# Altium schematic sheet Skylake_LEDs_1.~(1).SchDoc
size 431 x 279 mm; Date: Not shown in title block; ApprovedBy: Not shown in title block; CheckedBy: Not shown in title block; Author: Not shown in title block; CompanyName: Not shown in title block; Engineer: Not shown in title block; Organization: Not shown in title block; Address1: Not shown in title block; Address2: Not shown in title block; Address3: Not shown in title block; Address4: Not shown in title block; DocumentNumber: 1; Revision: Use project parameter SCH_Rev; SheetNumber: 5; SheetTotal: 9; PageSetup: Record=PageOptions|CenterHorizontal=True|CenterVertical=True|PrintScale=1.00|XCorrection=1.00|YCorrection=1.00|PrintKind=0|BorderSize=5000000|LeftOffset=0|BottomOffset=0|Orientation=2|PaperLength=1000|PaperWidth=1000|Scale=100|PaperSource=15|PrintQuality=600|MediaType=1|DitherType=10|PaperKind=Letter|PrintScaleMode=1
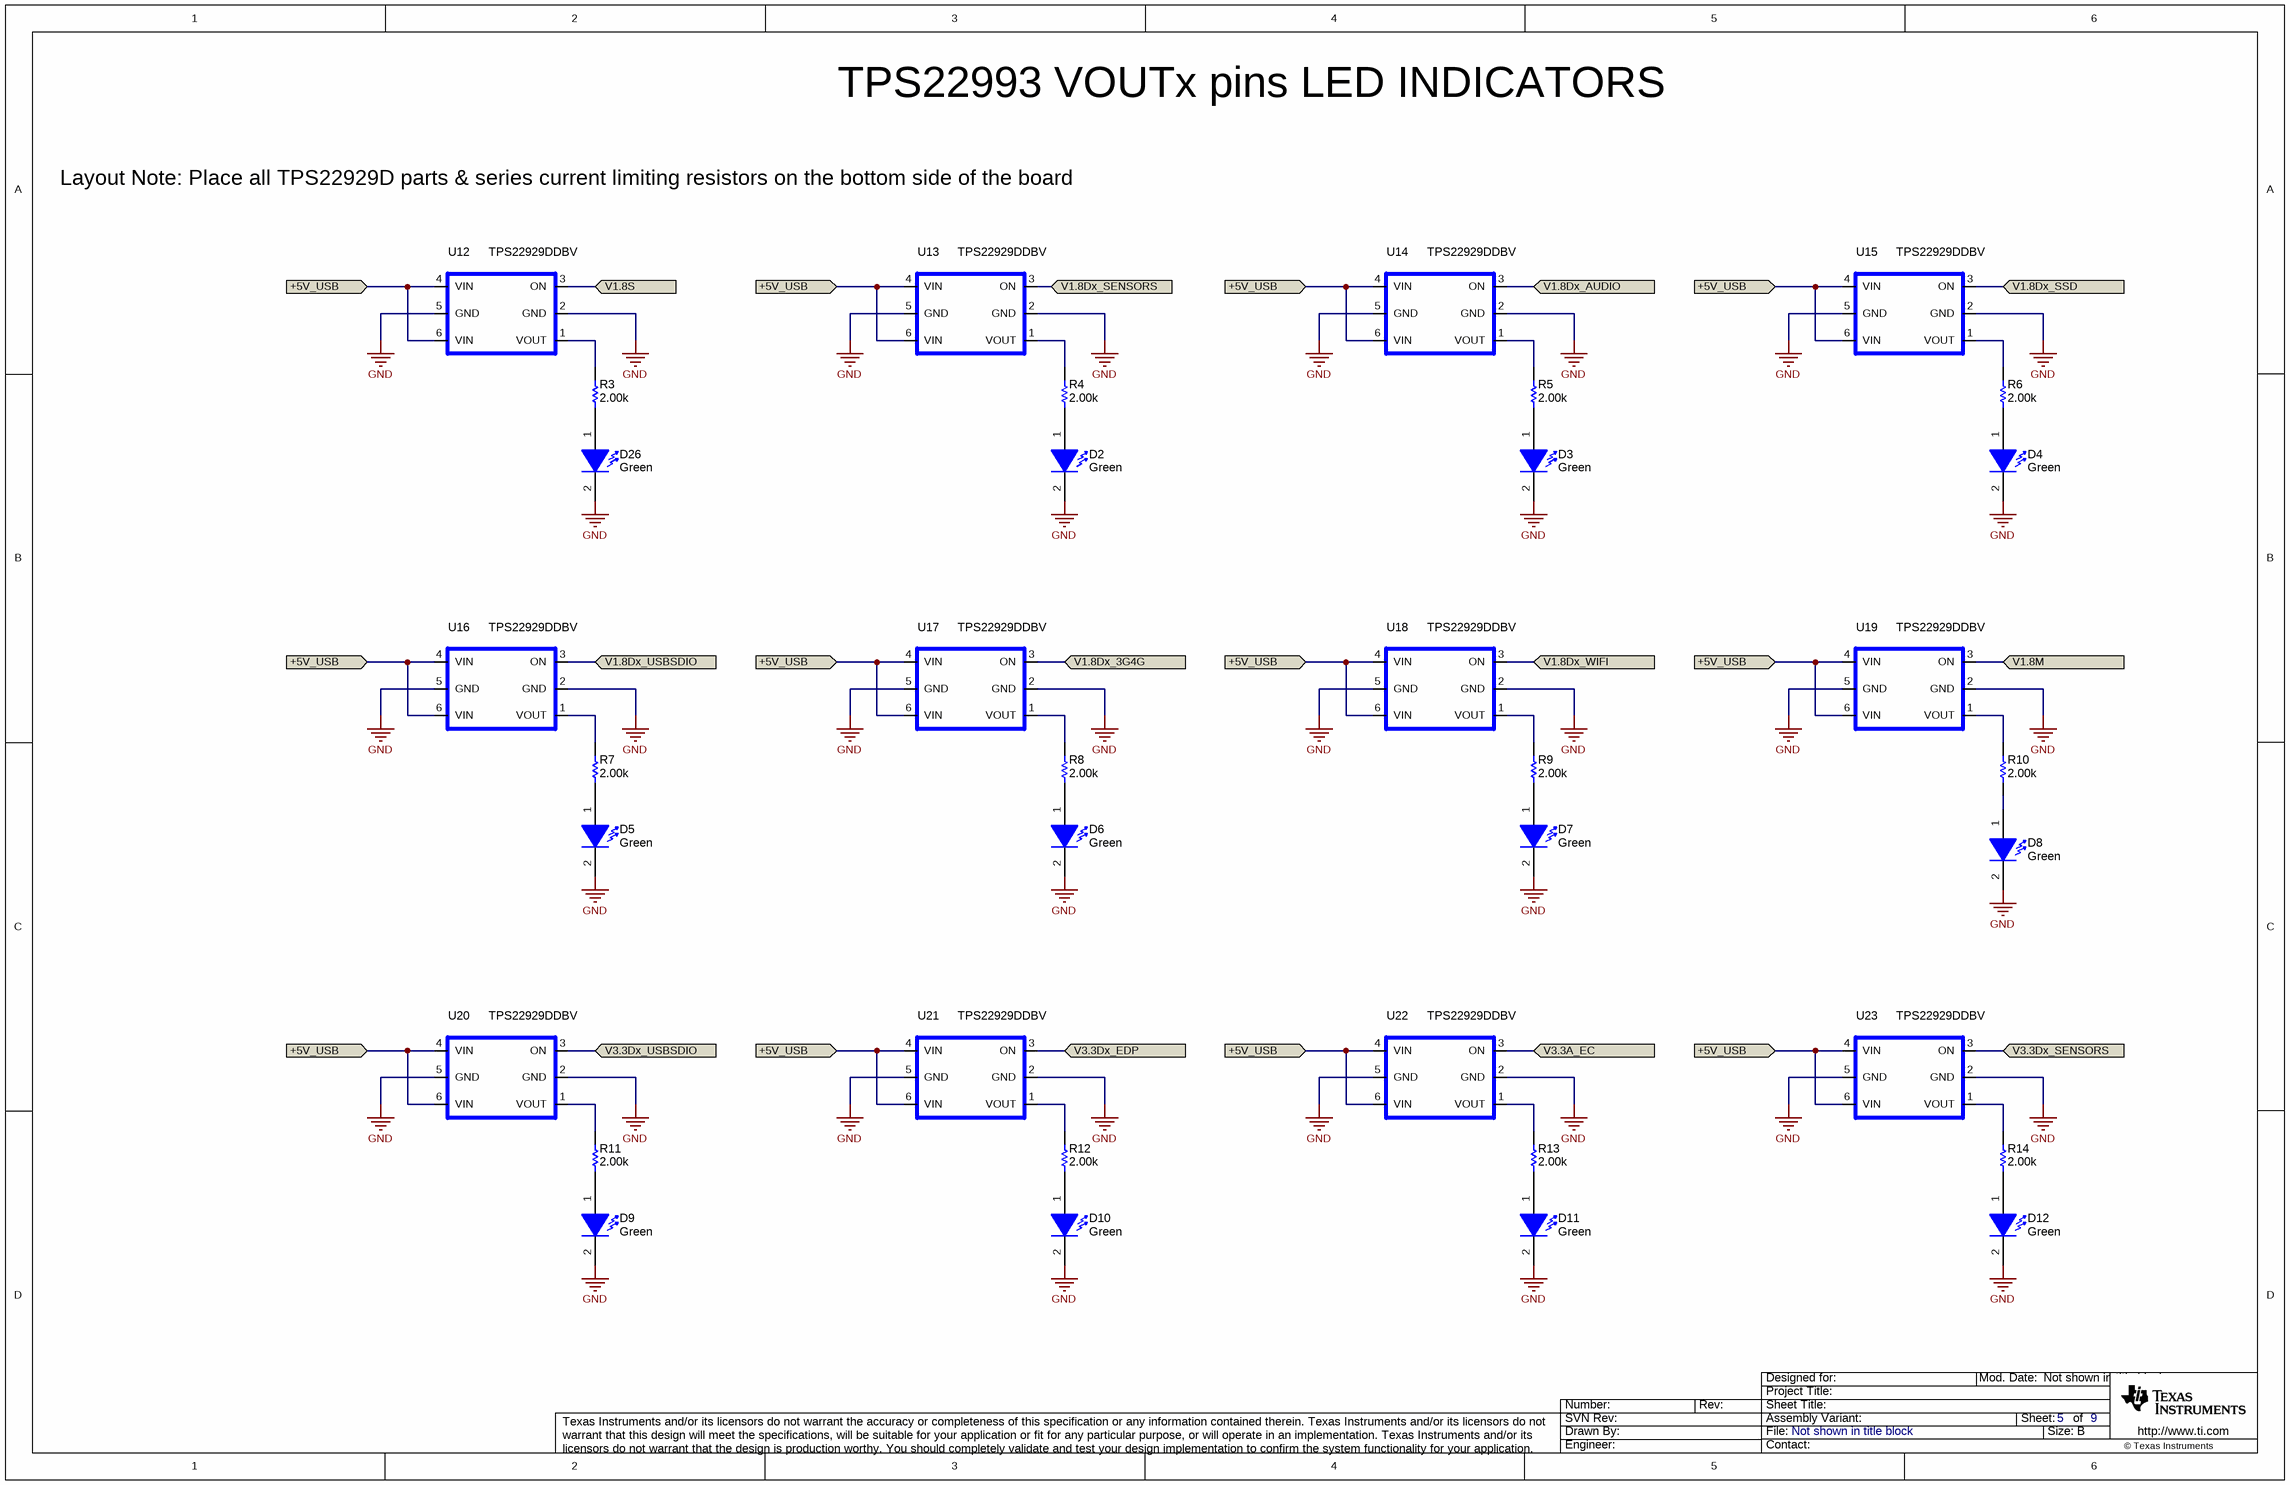
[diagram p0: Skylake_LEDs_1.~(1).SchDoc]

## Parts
D2  value Green  [LED_SML]  (hidden comment: SML312ECTT86)
D3  value Green  [LED_SML]  (hidden comment: SML312ECTT86)
D4  value Green  [LED_SML]  (hidden comment: SML312ECTT86)
D5  value Green  [LED_SML]  (hidden comment: SML312ECTT86)
D6  value Green  [LED_SML]  (hidden comment: SML312ECTT86)
D7  value Green  [LED_SML]  (hidden comment: SML312ECTT86)
D8  value Green  [LED_SML]  (hidden comment: SML312ECTT86)
D9  value Green  [LED_SML]  (hidden comment: SML312ECTT86)
D10  value Green  [LED_SML]  (hidden comment: SML312ECTT86)
D11  value Green  [LED_SML]  (hidden comment: SML312ECTT86)
D12  value Green  [LED_SML]  (hidden comment: SML312ECTT86)
D26  value Green  [LED_SML]  (hidden comment: SML312ECTT86)
R3  value 2.00k  [0603]  (hidden comment: CRCW06032K00FKEA)
R4  value 2.00k  [0603]  (hidden comment: CRCW06032K00FKEA)
R5  value 2.00k  [0603]  (hidden comment: CRCW06032K00FKEA)
R6  value 2.00k  [0603]  (hidden comment: CRCW06032K00FKEA)
R7  value 2.00k  [0603]  (hidden comment: CRCW06032K00FKEA)
R8  value 2.00k  [0603]  (hidden comment: CRCW06032K00FKEA)
R9  value 2.00k  [0603]  (hidden comment: CRCW06032K00FKEA)
R10  value 2.00k  [0603]  (hidden comment: CRCW06032K00FKEA)
R11  value 2.00k  [0603]  (hidden comment: CRCW06032K00FKEA)
R12  value 2.00k  [0603]  (hidden comment: CRCW06032K00FKEA)
R13  value 2.00k  [0603]  (hidden comment: CRCW06032K00FKEA)
R14  value 2.00k  [0603]  (hidden comment: CRCW06032K00FKEA)
U12  TPS22929DDBV  [DBV-6]
U13  TPS22929DDBV  [DBV-6]
U14  TPS22929DDBV  [DBV-6]
U15  TPS22929DDBV  [DBV-6]
U16  TPS22929DDBV  [DBV-6]
U17  TPS22929DDBV  [DBV-6]
U18  TPS22929DDBV  [DBV-6]
U19  TPS22929DDBV  [DBV-6]
U20  TPS22929DDBV  [DBV-6]
U21  TPS22929DDBV  [DBV-6]
U22  TPS22929DDBV  [DBV-6]
U23  TPS22929DDBV  [DBV-6]

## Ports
+5V_USB (in), V1.8Dx_3G4G (in), V1.8Dx_AUDIO (in), V1.8Dx_SENSORS (in), V1.8Dx_SSD (in), V1.8Dx_USBSDIO (in), V1.8Dx_WIFI (in), V1.8M (in), V1.8S (in), V3.3A_EC (in), V3.3Dx_EDP (in), V3.3Dx_SENSORS (in), V3.3Dx_USBSDIO (in)

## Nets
GND: D2.2(K) D3.2(K) D4.2(K) D5.2(K) D6.2(K) D7.2(K) D8.2(K) D9.2(K) D10.2(K) D11.2(K) D12.2(K) D26.2(K) U12.2(GND) U12.5(GND) U13.2(GND) U13.5(GND) U14.2(GND) U14.5(GND) U15.2(GND) U15.5(GND) U16.2(GND) U16.5(GND) U17.2(GND) U17.5(GND) U18.2(GND) U18.5(GND) U19.2(GND) U19.5(GND) U20.2(GND) U20.5(GND) U21.2(GND) U21.5(GND) U22.2(GND) U22.5(GND) U23.2(GND) U23.5(GND)
+5V_USB: U12.4(VIN) U12.6(VIN) U13.4(VIN) U13.6(VIN) U14.4(VIN) U14.6(VIN) U15.4(VIN) U15.6(VIN) U16.4(VIN) U16.6(VIN) U17.4(VIN) U17.6(VIN) U18.4(VIN) U18.6(VIN) U19.4(VIN) U19.6(VIN) U20.4(VIN) U20.6(VIN) U21.4(VIN) U21.6(VIN) U22.4(VIN) U22.6(VIN) U23.4(VIN) U23.6(VIN) ; port +5V_USB
V1.8Dx_3G4G: U17.3(ON) ; port V1.8Dx_3G4G
V1.8Dx_AUDIO: U14.3(ON) ; port V1.8Dx_AUDIO
V1.8Dx_SENSORS: U13.3(ON) ; port V1.8Dx_SENSORS
V1.8Dx_SSD: U15.3(ON) ; port V1.8Dx_SSD
V1.8Dx_USBSDIO: U16.3(ON) ; port V1.8Dx_USBSDIO
V1.8Dx_WIFI: U18.3(ON) ; port V1.8Dx_WIFI
V1.8M: U19.3(ON) ; port V1.8M
V1.8S: U12.3(ON) ; port V1.8S
V3.3A_EC: U22.3(ON) ; port V3.3A_EC
V3.3Dx_EDP: U21.3(ON) ; port V3.3Dx_EDP
V3.3Dx_SENSORS: U23.3(ON) ; port V3.3Dx_SENSORS
V3.3Dx_USBSDIO: U20.3(ON) ; port V3.3Dx_USBSDIO
NetD2_1: D2.1(A) R4.1
NetD3_1: D3.1(A) R5.1
NetD4_1: D4.1(A) R6.1
NetD5_1: D5.1(A) R7.1
NetD6_1: D6.1(A) R8.1
NetD7_1: D7.1(A) R9.1
NetD8_1: D8.1(A) R10.1
NetD9_1: D9.1(A) R11.1
NetD10_1: D10.1(A) R12.1
NetD11_1: D11.1(A) R13.1
NetD12_1: D12.1(A) R14.1
NetD26_1: D26.1(A) R3.1
NetR3_2: R3.2 U12.1(VOUT)
NetR4_2: R4.2 U13.1(VOUT)
NetR5_2: R5.2 U14.1(VOUT)
NetR6_2: R6.2 U15.1(VOUT)
NetR7_2: R7.2 U16.1(VOUT)
NetR8_2: R8.2 U17.1(VOUT)
NetR9_2: R9.2 U18.1(VOUT)
NetR10_2: R10.2 U19.1(VOUT)
NetR11_2: R11.2 U20.1(VOUT)
NetR12_2: R12.2 U21.1(VOUT)
NetR13_2: R13.2 U22.1(VOUT)
NetR14_2: R14.2 U23.1(VOUT)

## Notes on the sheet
- TPS22993 VOUTx pins LED INDICATORS
- Layout Note: Place all TPS22929D parts & series current limiting resistors on the bottom side of the board

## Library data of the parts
D2-D12 D26 = SML312WBCW1: LED, Green, SMD; Manufacturer: Rohm; Type: AlInGaP; ColorTemperature: 8000K; Vf_V: 3; Value2: 3V; Io_A: 0.005; Value1: W; U/M: EA
R3-R14 = CRCW06032K00FKEA: RES, 2.00k ohm, 1%, 0.1W, 0603; Manufacturer: Vishay-Dale; CompType: Resistor; Res_ohm: 2000; Value_Code: 2k00; Tolerance_%: 1; Power_W: 0.1; VDC_V: 75; TempCo: 100 ppm/C; EIA_Code: E96; U/M: EA
U12-U23 = TPS2292XDBV: IC, LOW INPUT VOLTAGE LOAD SWITCH  WITH CONTROLLED TURN-ON; Manufacturer: TI; Alternate Manufacturer: None; Area: 18.50 mm; Value: TPS22929DBV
